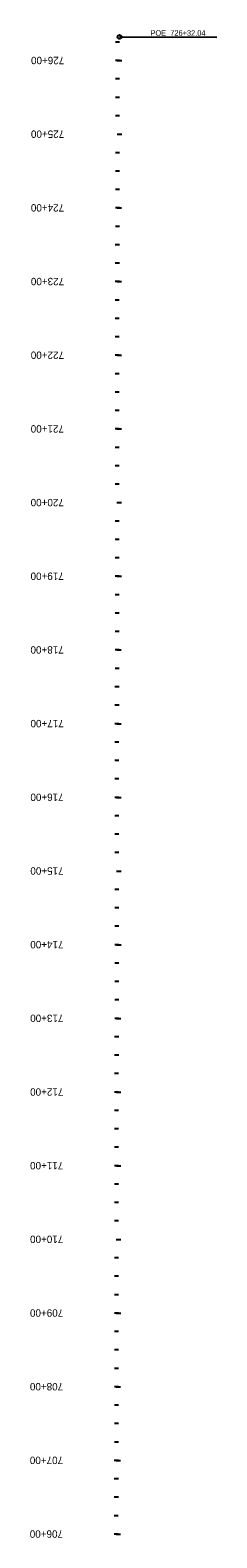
# Model space of a CAD drawing. Extents: x 16453950 to 16454580, y 7022804 to 7039381.
# Drawn here: x 16454327 to 16454580, y 7037335 to 7039381 of the extents above; entities that cross this region are included whole.
import ezdxf

# ---------------------------------------------------------------- set-up
doc = ezdxf.new("R2010")
doc.units = 0
for name, color, linetype in [('TextAlignment', 7, 'Continuous'), ('TextAlignmentLrg', 7, 'Continuous'), ('TextAlignmentSml', 7, 'Continuous')]:
    doc.layers.add(name, color=color, linetype=linetype)

msp = doc.modelspace()

# ---------------------------------------------------------------- linework, layer by layer
at = {"layer": 'TextAlignment'}
for p in [(16454448, 7039371.7), (16454580, 7039371.6)]:
    msp.add_line(p, (16454580, 7039371.6), dxfattribs=at)
msp.add_circle((16454448, 7039371.7), 2.67, dxfattribs=at)
at = {"layer": 'TextAlignmentLrg'}
for p, q in [((16454448, 7039339.6), (16454442.5, 7039339.6)), ((16454444.9, 7039239.6), (16454451, 7039239.6)), ((16454447.8, 7039139.6), (16454442.4, 7039139.6)), ((16454447.8, 7039039.6), (16454442.3, 7039039.6)), ((16454447.7, 7038939.6), (16454442.2, 7038939.6)), ((16454447.6, 7038839.6), (16454442.1, 7038839.6)), ((16454444.4, 7038739.6), (16454450.6, 7038739.6)), ((16454447.4, 7038639.6), (16454442, 7038639.6)), ((16454447.3, 7038539.6), (16454441.9, 7038539.6)), ((16454447.2, 7038439.6), (16454441.8, 7038439.6)), ((16454447.2, 7038339.6), (16454441.7, 7038339.6)), ((16454444, 7038239.6), (16454450.1, 7038239.6)), ((16454447, 7038139.6), (16454441.5, 7038139.6)), ((16454446.9, 7038039.6), (16454441.5, 7038039.6)), ((16454446.8, 7037939.6), (16454441.4, 7037939.6)), ((16454446.7, 7037839.6), (16454441.3, 7037839.6)), ((16454443.6, 7037739.6), (16454449.7, 7037739.6)), ((16454446.6, 7037639.6), (16454441.1, 7037639.6)), ((16454446.5, 7037539.6), (16454441, 7037539.6)), ((16454446.4, 7037439.6), (16454440.9, 7037439.6)), ((16454446.3, 7037339.6), (16454440.9, 7037339.6))]:
    msp.add_line(p, q, dxfattribs=at)
at = {"layer": 'TextAlignmentSml'}
for p, q in [((16454448, 7039364.6), (16454442.6, 7039364.6)), ((16454444.9, 7039339.6), (16454451.1, 7039339.6)), ((16454448, 7039314.6), (16454442.5, 7039314.6)), ((16454448, 7039289.6), (16454442.5, 7039289.6)), ((16454447.9, 7039264.6), (16454442.5, 7039264.6)), ((16454444.9, 7039239.6), (16454451, 7039239.6)), ((16454447.9, 7039214.6), (16454442.4, 7039214.6)), ((16454447.9, 7039189.6), (16454442.4, 7039189.6)), ((16454447.9, 7039164.6), (16454442.4, 7039164.6)), ((16454444.8, 7039139.6), (16454450.9, 7039139.6)), ((16454447.8, 7039114.6), (16454442.4, 7039114.6)), ((16454447.8, 7039089.6), (16454442.3, 7039089.6)), ((16454447.8, 7039064.6), (16454442.3, 7039064.6)), ((16454444.7, 7039039.6), (16454450.8, 7039039.6)), ((16454447.7, 7039014.6), (16454442.3, 7039014.6)), ((16454447.7, 7038989.6), (16454442.3, 7038989.6)), ((16454447.7, 7038964.6), (16454442.2, 7038964.6)), ((16454444.6, 7038939.6), (16454450.7, 7038939.6)), ((16454447.6, 7038914.6), (16454442.2, 7038914.6)), ((16454447.6, 7038889.6), (16454442.2, 7038889.6)), ((16454447.6, 7038864.6), (16454442.1, 7038864.6)), ((16454444.5, 7038839.6), (16454450.6, 7038839.6)), ((16454447.6, 7038814.6), (16454442.1, 7038814.6)), ((16454447.5, 7038789.6), (16454442.1, 7038789.6)), ((16454447.5, 7038764.6), (16454442.1, 7038764.6)), ((16454444.4, 7038739.6), (16454450.6, 7038739.6)), ((16454447.5, 7038714.6), (16454442, 7038714.6)), ((16454447.5, 7038689.6), (16454442, 7038689.6)), ((16454447.4, 7038664.6), (16454442, 7038664.6)), ((16454444.4, 7038639.6), (16454450.5, 7038639.6)), ((16454447.4, 7038614.6), (16454441.9, 7038614.6)), ((16454447.4, 7038589.6), (16454441.9, 7038589.6)), ((16454447.4, 7038564.6), (16454441.9, 7038564.6)), ((16454444.3, 7038539.6), (16454450.4, 7038539.6)), ((16454447.3, 7038514.6), (16454441.9, 7038514.6)), ((16454447.3, 7038489.6), (16454441.8, 7038489.6)), ((16454447.3, 7038464.6), (16454441.8, 7038464.6)), ((16454444.2, 7038439.6), (16454450.3, 7038439.6)), ((16454447.2, 7038414.6), (16454441.8, 7038414.6)), ((16454447.2, 7038389.6), (16454441.7, 7038389.6)), ((16454447.2, 7038364.6), (16454441.7, 7038364.6)), ((16454444.1, 7038339.6), (16454450.2, 7038339.6)), ((16454447.1, 7038314.6), (16454441.7, 7038314.6)), ((16454447.1, 7038289.6), (16454441.7, 7038289.6)), ((16454447.1, 7038264.6), (16454441.6, 7038264.6)), ((16454444, 7038239.6), (16454450.1, 7038239.6)), ((16454447.1, 7038214.6), (16454441.6, 7038214.6)), ((16454447, 7038189.6), (16454441.6, 7038189.6)), ((16454447, 7038164.6), (16454441.6, 7038164.6)), ((16454443.9, 7038139.6), (16454450.1, 7038139.6)), ((16454447, 7038114.6), (16454441.5, 7038114.6)), ((16454447, 7038089.6), (16454441.5, 7038089.6)), ((16454446.9, 7038064.6), (16454441.5, 7038064.6)), ((16454443.9, 7038039.6), (16454450, 7038039.6)), ((16454446.9, 7038014.6), (16454441.4, 7038014.6)), ((16454446.9, 7037989.6), (16454441.4, 7037989.6)), ((16454446.8, 7037964.6), (16454441.4, 7037964.6)), ((16454443.8, 7037939.6), (16454449.9, 7037939.6)), ((16454446.8, 7037914.6), (16454441.3, 7037914.6)), ((16454446.8, 7037889.6), (16454441.3, 7037889.6)), ((16454446.8, 7037864.6), (16454441.3, 7037864.6)), ((16454443.7, 7037839.6), (16454449.8, 7037839.6)), ((16454446.7, 7037814.6), (16454441.3, 7037814.6)), ((16454446.7, 7037789.6), (16454441.2, 7037789.6)), ((16454446.7, 7037764.6), (16454441.2, 7037764.6)), ((16454443.6, 7037739.6), (16454449.7, 7037739.6)), ((16454446.6, 7037714.6), (16454441.2, 7037714.6)), ((16454446.6, 7037689.6), (16454441.2, 7037689.6)), ((16454446.6, 7037664.6), (16454441.1, 7037664.6)), ((16454443.5, 7037639.6), (16454449.6, 7037639.6)), ((16454446.6, 7037614.6), (16454441.1, 7037614.6)), ((16454446.5, 7037589.6), (16454441.1, 7037589.6)), ((16454446.5, 7037564.6), (16454441.1, 7037564.6)), ((16454443.4, 7037539.6), (16454449.5, 7037539.6)), ((16454446.5, 7037514.6), (16454441, 7037514.6)), ((16454446.4, 7037489.6), (16454441, 7037489.6)), ((16454446.4, 7037464.6), (16454441, 7037464.6)), ((16454443.3, 7037439.6), (16454449.5, 7037439.6)), ((16454446.4, 7037414.6), (16454440.9, 7037414.6)), ((16454446.4, 7037389.6), (16454440.9, 7037389.6)), ((16454446.3, 7037364.6), (16454440.9, 7037364.6)), ((16454443.3, 7037339.6), (16454449.4, 7037339.6))]:
    msp.add_line(p, q, dxfattribs=at)

# ---------------------------------------------------------------- texts
at = {"layer": 'TextAlignment'}
for s, p in [('POE ', (16454490, 7039373.3)), ('726+32.04', (16454516.9, 7039373.3))]:
    msp.add_text(s, height=7.5, rotation=359.9517, dxfattribs=at).set_placement(p)
at = {"layer": 'TextAlignmentLrg'}
for s, p in [('725+00', (16454372.9, 7039244.7)), ('720+00', (16454372.5, 7038744.7)), ('715+00', (16454372.1, 7038244.7)), ('710+00', (16454371.7, 7037744.7))]:
    msp.add_text(s, height=10.02, rotation=179.9517, dxfattribs=at).set_placement(p)
at = {"layer": 'TextAlignmentSml'}
for s, p in [('726+00', (16454373, 7039344.7)), ('725+00', (16454372.9, 7039244.7)), ('724+00', (16454372.8, 7039144.7)), ('723+00', (16454372.8, 7039044.7)), ('722+00', (16454372.7, 7038944.7)), ('721+00', (16454372.6, 7038844.7)), ('720+00', (16454372.5, 7038744.7)), ('719+00', (16454372.4, 7038644.7)), ('718+00', (16454372.3, 7038544.7)), ('717+00', (16454372.3, 7038444.7)), ('716+00', (16454372.2, 7038344.7)), ('715+00', (16454372.1, 7038244.7)), ('714+00', (16454372, 7038144.7)), ('713+00', (16454371.9, 7038044.7)), ('712+00', (16454371.8, 7037944.7)), ('711+00', (16454371.7, 7037844.7)), ('710+00', (16454371.7, 7037744.7)), ('709+00', (16454371.6, 7037644.7)), ('708+00', (16454371.5, 7037544.7)), ('707+00', (16454371.4, 7037444.7)), ('706+00', (16454371.3, 7037344.7))]:
    msp.add_text(s, height=10.02, rotation=179.9517, dxfattribs=at).set_placement(p)

doc.saveas('drawing.dxf')
